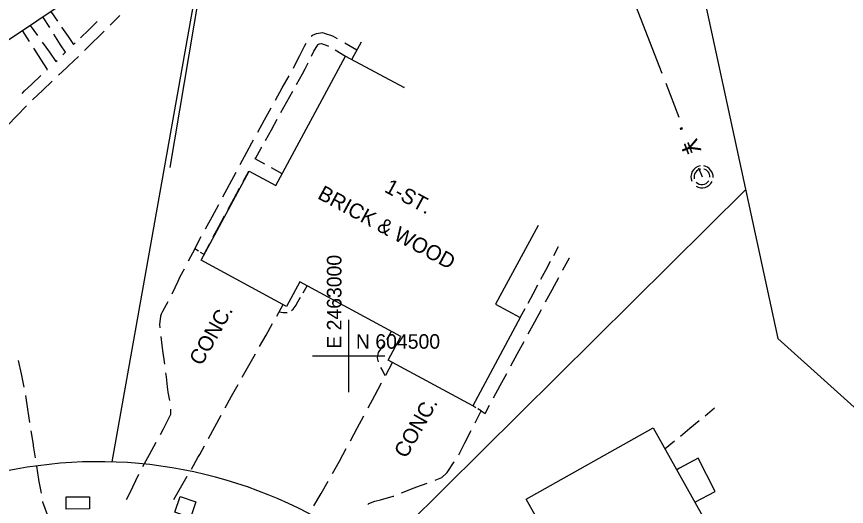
# Model space of a CAD drawing. Extents: x 2443269 to 2494951, y 591171 to 622130.
# Drawn here: x 2462908.5 to 2463137.2, y 604458.5 to 604593.6 of the extents above; entities that cross this region are included whole.
import ezdxf

# ---------------------------------------------------------------- set-up
doc = ezdxf.new("R2010")
doc.units = 0
for name, color, linetype in [('SURVEY - CENTERLINE - Existing Roads', 7, 'Continuous'), ('SURVEY - CONTROL - Grid', 7, 'Continuous'), ('SURVEY - CONTROL - Grid Text', 7, 'Continuous'), ('SURVEY - NON-TRANSPORTATION - Buildings', 7, 'Continuous'), ('SURVEY - NON-TRANSPORTATION - Buildings Text', 7, 'Continuous'), ('SURVEY - NON-TRANSPORTATION - Features', 7, 'Continuous'), ('SURVEY - PROPERTY - Property Lines', 7, 'Continuous'), ('SURVEY - PROPERTY - ROW Lines', 7, 'Continuous'), ('SURVEY - TRANSPORTATION - Features', 7, 'Continuous'), ('SURVEY - TRANSPORTATION - Features Text', 7, 'Continuous'), ('SURVEY - TRANSPORTATION - Roads', 7, 'Continuous'), ('SURVEY - UTILITIES - Cable (Underground) with Text', 7, 'Continuous'), ('SURVEY - UTILITIES - Poles and Miscellaneous with Text', 7, 'Continuous'), ('SURVEY - UTILITIES - Sanitary Sewer with Text', 7, 'Continuous')]:
    doc.layers.add(name, color=color, linetype=linetype)

# ---------------------------------------------------------------- blocks, each defined once
blk = doc.blocks.new('xlp')
at = {"layer": 'SURVEY - UTILITIES - Cable (Underground) with Text'}
for p, q in [((9.374, 2.317), (9.033, 2.131)), ((9.74, 2.449), (9.374, 2.317)), ((9.374, 2.317), (9.374, 2.317)), ((10.122, 2.523), (9.74, 2.449)), ((9.74, 2.449), (9.74, 2.449)), ((10.511, 2.538), (10.122, 2.523)), ((10.122, 2.523), (10.122, 2.523)), ((10.897, 2.493), (10.511, 2.538)), ((10.511, 2.538), (10.511, 2.538)), ((11.272, 2.39), (10.897, 2.493)), ((10.897, 2.493), (10.897, 2.493)), ((11.627, 2.231), (11.272, 2.39)), ((11.272, 2.39), (11.272, 2.39)), ((-2.285, -2.285), (-2.285, 2.285)), ((-2.285, 2.285), (-2.285, 2.285)), ((-2.285, 2.285), (2.285, 2.285)), ((2.285, 2.285), (2.285, -2.285)), ((2.285, 0), (7.873, 0)), ((7.94, 0.578), (7.881, 0.194)), ((7.881, 0.194), (7.881, 0.194)), ((7.881, 0.194), (7.881, -0.194)), ((8.058, 0.949), (7.94, 0.578)), ((7.94, 0.578), (7.94, 0.578)), ((8.23, 1.297), (8.058, 0.949)), ((8.058, 0.949), (8.058, 0.949)), ((8.454, 1.616), (8.23, 1.297)), ((8.23, 1.297), (8.23, 1.297)), ((8.724, 1.896), (8.454, 1.616)), ((8.454, 1.616), (8.454, 1.616)), ((9.033, 2.131), (8.724, 1.896)), ((8.724, 1.896), (8.724, 1.896)), ((9.033, 2.131), (9.033, 2.131)), ((11.953, 2.02), (11.627, 2.231)), ((11.627, 2.231), (11.627, 2.231)), ((12.244, 1.761), (11.953, 2.02)), ((11.953, 2.02), (11.953, 2.02)), ((12.491, 1.461), (12.244, 1.761)), ((12.244, 1.761), (12.244, 1.761)), ((12.69, 1.127), (12.491, 1.461)), ((12.491, 1.461), (12.491, 1.461)), ((12.835, 0.766), (12.69, 1.127)), ((12.69, 1.127), (12.69, 1.127)), ((12.924, 0.387), (12.835, 0.766)), ((12.835, 0.766), (12.835, 0.766)), ((12.953, 0), (12.924, 0.387)), ((12.924, 0.387), (12.924, 0.387)), ((12.924, -0.387), (12.953, 0)), ((2.285, -2.285), (-2.285, -2.285)), ((-2.285, -2.285), (-2.285, -2.285)), ((2.285, -2.285), (2.285, -2.285)), ((7.881, -0.194), (7.881, -0.194)), ((7.881, -0.194), (7.94, -0.578)), ((7.94, -0.578), (7.94, -0.578)), ((7.94, -0.578), (8.058, -0.949)), ((8.058, -0.949), (8.058, -0.949)), ((8.058, -0.949), (8.23, -1.297)), ((8.23, -1.297), (8.23, -1.297)), ((8.23, -1.297), (8.454, -1.616)), ((8.454, -1.616), (8.454, -1.616)), ((8.454, -1.616), (8.724, -1.896)), ((8.724, -1.896), (8.724, -1.896)), ((8.724, -1.896), (9.033, -2.131)), ((9.033, -2.131), (9.033, -2.131)), ((9.033, -2.131), (9.374, -2.317)), ((11.272, -2.39), (11.627, -2.231)), ((11.627, -2.231), (11.953, -2.02)), ((11.627, -2.231), (11.627, -2.231)), ((11.953, -2.02), (12.244, -1.761)), ((11.953, -2.02), (11.953, -2.02)), ((12.244, -1.761), (12.491, -1.461)), ((12.244, -1.761), (12.244, -1.761)), ((12.491, -1.461), (12.69, -1.127)), ((12.491, -1.461), (12.491, -1.461)), ((12.69, -1.127), (12.835, -0.766)), ((12.69, -1.127), (12.69, -1.127)), ((12.835, -0.766), (12.924, -0.387)), ((12.835, -0.766), (12.835, -0.766)), ((12.924, -0.387), (12.924, -0.387)), ((9.374, -2.317), (9.374, -2.317)), ((9.374, -2.317), (9.74, -2.449)), ((9.74, -2.449), (9.74, -2.449)), ((9.74, -2.449), (10.122, -2.523)), ((10.122, -2.523), (10.122, -2.523)), ((10.122, -2.523), (10.511, -2.538)), ((10.511, -2.538), (10.897, -2.493)), ((10.511, -2.538), (10.511, -2.538)), ((10.897, -2.493), (11.272, -2.39)), ((10.897, -2.493), (10.897, -2.493)), ((11.272, -2.39), (11.272, -2.39))]:
    blk.add_line(p, q, dxfattribs=at)
blk = doc.blocks.new('xmh')
at = {"layer": 'SURVEY - CENTERLINE - Existing Roads'}
for p, q in [((-1.773, 2.501), (-2.286, 2.034)), ((-1.171, 2.844), (-1.773, 2.501)), ((-1.773, 2.501), (-1.773, 2.501)), ((-0.508, 3.048), (-1.171, 2.844)), ((-1.171, 2.844), (-1.171, 2.844)), ((1.042, 2.883), (0.508, 3.048)), ((1.539, 2.628), (1.042, 2.883)), ((1.042, 2.883), (1.042, 2.883)), ((1.985, 2.291), (1.539, 2.628)), ((1.539, 2.628), (1.539, 2.628)), ((2.366, 1.882), (1.985, 2.291)), ((1.985, 2.291), (1.985, 2.291)), ((-2.948, 0.825), (-3.065, 0.141)), ((-3.065, 0.141), (-3.065, 0.141)), ((-3.065, 0.141), (-3.03, -0.551)), ((-2.684, 1.466), (-2.948, 0.825)), ((-2.948, 0.825), (-2.948, 0.825)), ((-2.286, 2.034), (-2.684, 1.466)), ((-2.684, 1.466), (-2.684, 1.466)), ((-2.286, 2.034), (-2.286, 2.034)), ((-2.167, 0.395), (-2.198, -0.058)), ((-2.039, 0.831), (-2.167, 0.395)), ((-2.167, 0.395), (-2.167, 0.395)), ((-1.822, 1.23), (-2.039, 0.831)), ((-2.039, 0.831), (-2.039, 0.831)), ((-1.525, 1.574), (-1.822, 1.23)), ((-1.822, 1.23), (-1.822, 1.23)), ((-1.161, 1.847), (-1.525, 1.574)), ((-1.525, 1.574), (-1.525, 1.574)), ((-0.748, 2.036), (-1.161, 1.847)), ((-1.161, 1.847), (-1.161, 1.847)), ((-0.304, 2.133), (-0.748, 2.036)), ((-0.748, 2.036), (-0.748, 2.036)), ((0.864, 2.014), (0.508, 2.133)), ((1.194, 1.835), (0.864, 2.014)), ((0.864, 2.014), (0.864, 2.014)), ((1.487, 1.599), (1.194, 1.835)), ((1.194, 1.835), (1.194, 1.835)), ((1.734, 1.316), (1.487, 1.599)), ((1.487, 1.599), (1.487, 1.599)), ((1.927, 0.994), (1.734, 1.316)), ((1.734, 1.316), (1.734, 1.316)), ((2.061, 0.643), (1.927, 0.994)), ((1.927, 0.994), (1.927, 0.994)), ((2.13, 0.274), (2.061, 0.643)), ((2.061, 0.643), (2.061, 0.643)), ((2.133, -0.101), (2.13, 0.274)), ((2.13, 0.274), (2.13, 0.274)), ((2.671, 1.413), (2.366, 1.882)), ((2.366, 1.882), (2.366, 1.882)), ((2.89, 0.899), (2.671, 1.413)), ((2.671, 1.413), (2.671, 1.413)), ((3.017, 0.354), (2.89, 0.899)), ((2.89, 0.899), (2.89, 0.899)), ((3.048, -0.203), (3.017, 0.354)), ((3.017, 0.354), (3.017, 0.354)), ((-3.03, -0.551), (-3.03, -0.551)), ((-3.03, -0.551), (-2.844, -1.219)), ((-2.198, -0.058), (-2.198, -0.058)), ((-2.198, -0.058), (-2.133, -0.508)), ((-1.625, -1.422), (-1.25, -1.756)), ((-1.25, -1.756), (-1.25, -1.756)), ((-1.25, -1.756), (-0.808, -1.995)), ((-0.808, -1.995), (-0.808, -1.995)), ((-0.808, -1.995), (-0.323, -2.125)), ((-0.323, -2.125), (-0.323, -2.125)), ((-0.323, -2.125), (0.178, -2.14)), ((0.178, -2.14), (0.67, -2.038)), ((0.178, -2.14), (0.178, -2.14)), ((0.67, -2.038), (1.125, -1.825)), ((0.67, -2.038), (0.67, -2.038)), ((1.125, -1.825), (1.518, -1.512)), ((1.125, -1.825), (1.125, -1.825)), ((1.518, -1.512), (1.828, -1.117)), ((1.518, -1.512), (1.518, -1.512)), ((1.958, -2.32), (2.403, -1.862)), ((2.403, -1.862), (2.743, -1.32)), ((2.403, -1.862), (2.403, -1.862)), ((-1.625, -2.54), (-1.054, -2.827)), ((-1.054, -2.827), (-1.054, -2.827)), ((-1.054, -2.827), (-0.436, -2.988)), ((-0.436, -2.988), (-0.436, -2.988)), ((-0.436, -2.988), (0.202, -3.016)), ((0.202, -3.016), (0.832, -2.91)), ((0.202, -3.016), (0.202, -3.016)), ((0.832, -2.91), (1.426, -2.675)), ((0.832, -2.91), (0.832, -2.91)), ((1.426, -2.675), (1.958, -2.32)), ((1.426, -2.675), (1.426, -2.675)), ((1.958, -2.32), (1.958, -2.32))]:
    blk.add_line(p, q, dxfattribs=at)

msp = doc.modelspace()

# ---------------------------------------------------------------- linework, layer by layer
at = {"layer": 'SURVEY - CONTROL - Grid'}
for p, q in [((2463000, 604490), (2463000, 604510)), ((2462990, 604500), (2463010, 604500))]:
    msp.add_line(p, q, dxfattribs=at)
at = {"layer": 'SURVEY - NON-TRANSPORTATION - Buildings'}
for points in [[(2462848.145, 604606.514), (2462872.072, 604622.541), (2462871.238, 604623.785), (2462901.603, 604644.126), (2462902.741, 604642.423), (2462925.864, 604657.912), (2462953.292, 604616.967), (2462929.568, 604601.075), (2462928.768, 604602.269), (2462899.28, 604582.515), (2462899.709, 604581.872), (2462875.51, 604565.661)], [(2463082.619, 604400.324), (2463048.889, 604460.498), (2463083.948, 604480.15), (2463117.678, 604419.976)]]:
    msp.add_lwpolyline(points, close=True, dxfattribs=at)
msp.add_lwpolyline([(2463052.212, 604535.993), (2463040.48, 604514.247), (2463047.311, 604510.563), (2463034.188, 604486.239), (2463010.864, 604498.821), (2463014.414, 604505.402), (2462986.553, 604520.435), (2462982.905, 604513.67), (2462959.335, 604526.387)], dxfattribs=at)
at = {"layer": 'SURVEY - NON-TRANSPORTATION - Buildings Text'}
msp.add_lwpolyline([(2462959.335, 604526.387), (2462972.613, 604550.996), (2462979.913, 604547.059), (2462999.158, 604582.732), (2463015.251, 604574.051), (2463015.339, 604574.215)], dxfattribs=at)
at = {"layer": 'SURVEY - NON-TRANSPORTATION - Features'}
for p, q in [((2462950.766, 604551.977), (2462963.315, 604626.111)), ((2463003.426, 604586.567), (2463000.851, 604581.908)), ((2463091.153, 604469.08), (2463090.441, 604468.568))]:
    msp.add_line(p, q, dxfattribs=at)
msp.add_lwpolyline([(2463095.408, 604459.704), (2463101.064, 604462.633), (2463096.336, 604471.764), (2463091.153, 604469.08)], dxfattribs=at)
msp.add_lwpolyline([(2462922.121, 604461.101), (2462928.535, 604461.154), (2462928.561, 604457.837), (2462922.147, 604457.784)], close=True, dxfattribs=at)
at = {"layer": 'SURVEY - PROPERTY - Property Lines'}
for p, q in [((2462934.798, 604470.777), (2462984.933, 604752.663)), ((2463007.39, 604444.738), (2463109.405, 604545.802))]:
    msp.add_line(p, q, dxfattribs=at)
msp.add_lwpolyline([(2462970.603, 604768.156), (2463088.693, 604641.661), (2463118.316, 604504.82), (2463394.014, 604256.663)], dxfattribs=at)
at = {"layer": 'SURVEY - PROPERTY - ROW Lines'}
msp.add_arc((2462930.948, 604345.836), 124.999, 41.29809, 131.29837, dxfattribs=at)
at = {"layer": 'SURVEY - TRANSPORTATION - Features'}
for p, q in [((2462917.905, 604594.992), (2462919.734, 604592.358)), ((2462917.583, 604590.591), (2462915.723, 604593.529)), ((2462915.723, 604593.529), (2462915.723, 604593.529)), ((2462934.23, 604591.216), (2462936.897, 604593.881)), ((2462912.229, 604591.19), (2462914.247, 604588.357)), ((2462920.877, 604590.711), (2462922.706, 604588.077)), ((2462928.37, 604589.998), (2462930.639, 604592.265)), ((2462911.986, 604586.727), (2462910.044, 604589.726)), ((2462910.044, 604589.726), (2462910.044, 604589.726)), ((2462920.606, 604585.816), (2462918.746, 604588.754)), ((2462922.706, 604588.077), (2462924.185, 604585.947)), ((2462926.066, 604587.768), (2462928.364, 604589.992)), ((2462928.364, 604589.992), (2462928.37, 604589.998)), ((2462930.664, 604587.653), (2462932.563, 604589.55)), ((2462989.693, 604588.185), (2462990.031, 604588.516)), ((2462990.031, 604588.516), (2462991.13, 604588.959)), ((2462991.13, 604588.959), (2462992.777, 604589.215)), ((2462992.777, 604589.215), (2462993.277, 604589.042)), ((2462993.277, 604589.042), (2462995.503, 604588.273)), ((2462995.503, 604588.273), (2462996.807, 604587.535)), ((2462915.508, 604586.587), (2462917.526, 604583.755)), ((2462921.914, 604583.749), (2462920.606, 604585.816)), ((2462924.185, 604585.947), (2462924.626, 604586.374)), ((2462927.174, 604584.275), (2462929.884, 604586.898)), ((2462929.884, 604586.898), (2462930.664, 604587.653)), ((2462987.81, 604585.438), (2462988.293, 604586.248)), ((2462990.405, 604584.024), (2462991.38, 604585.656)), ((2462991.38, 604585.656), (2462991.448, 604585.77)), ((2462991.448, 604585.77), (2462991.678, 604585.996)), ((2462991.678, 604585.996), (2462991.917, 604586.094)), ((2462991.917, 604586.094), (2462992.505, 604586.183)), ((2462992.505, 604586.183), (2462994.293, 604585.566)), ((2462994.293, 604585.566), (2462994.435, 604585.483)), ((2462998.902, 604586.349), (2463002.255, 604584.451)), ((2462915.141, 604581.854), (2462913.199, 604584.853)), ((2462917.526, 604583.755), (2462919.309, 604581.252)), ((2462921.173, 604583.032), (2462921.914, 604583.749)), ((2462986.517, 604582.831), (2462987.81, 604585.438)), ((2462989.755, 604582.713), (2462990.405, 604584.024)), ((2462996.251, 604584.425), (2462999.158, 604582.732)), ((2463002.255, 604584.451), (2463002.255, 604584.451)), ((2462916.96, 604579.044), (2462915.141, 604581.854)), ((2462919.309, 604581.252), (2462919.604, 604581.529)), ((2462922.771, 604580.015), (2462925.481, 604582.637)), ((2462985.382, 604580.54), (2462986.517, 604582.831)), ((2462999.158, 604582.732), (2462999.158, 604582.732)), ((2462916.796, 604578.89), (2462916.96, 604579.044)), ((2462920.03, 604577.426), (2462922.328, 604579.585)), ((2462922.328, 604579.585), (2462922.771, 604580.015)), ((2462984.752, 604579.407), (2462985.382, 604580.54)), ((2462987.265, 604577.849), (2462987.997, 604579.165)), ((2462987.997, 604579.165), (2462988.822, 604580.83)), ((2462912.566, 604574.913), (2462915.169, 604577.36)), ((2462981.71, 604573.935), (2462983.582, 604577.303)), ((2462985.631, 604574.908), (2462987.265, 604577.849)), ((2462910.658, 604573.119), (2462912.566, 604574.913)), ((2462915.566, 604573.229), (2462918.313, 604575.811)), ((2462909.994, 604572.435), (2462910.658, 604573.119)), ((2462912.961, 604570.78), (2462915.566, 604573.229)), ((2462979.839, 604570.567), (2462981.71, 604573.935)), ((2462982.975, 604570.13), (2462984.609, 604573.071)), ((2462912.825, 604570.64), (2462912.961, 604570.78)), ((2462981.341, 604567.19), (2462982.975, 604570.13)), ((2462908.559, 604566.242), (2462911.184, 604568.948)), ((2462976.797, 604565.095), (2462978.669, 604568.462)), ((2462905.934, 604563.536), (2462908.559, 604566.242)), ((2462974.925, 604561.727), (2462976.797, 604565.095)), ((2462978.685, 604562.412), (2462980.319, 604565.352)), ((2462977.051, 604559.472), (2462978.685, 604562.412)), ((2462971.918, 604556.235), (2462973.282, 604558.772)), ((2462973.282, 604558.772), (2462973.755, 604559.622)), ((2462970.094, 604552.841), (2462971.918, 604556.235)), ((2462974.432, 604554.674), (2462975.874, 604557.354)), ((2462975.874, 604557.354), (2462976.029, 604557.634)), ((2462974.247, 604554.329), (2462974.432, 604554.674)), ((2462976.848, 604552.89), (2462974.247, 604554.329)), ((2462981.632, 604550.245), (2462978.688, 604551.873)), ((2462967.129, 604547.327), (2462968.954, 604550.72)), ((2462970.887, 604548.078), (2462972.449, 604550.983)), ((2462972.449, 604550.983), (2462972.449, 604550.983)), ((2462965.305, 604543.933), (2462967.129, 604547.327)), ((2462968.349, 604543.358), (2462969.911, 604546.263)), ((2462966.787, 604540.454), (2462968.349, 604543.358)), ((2462962.34, 604538.418), (2462964.164, 604541.812)), ((2462960.515, 604535.025), (2462962.34, 604538.418)), ((2462964.249, 604535.734), (2462965.811, 604538.638)), ((2462962.687, 604532.829), (2462964.249, 604535.734)), ((2462957.551, 604529.51), (2462959.375, 604532.904)), ((2462960.149, 604528.109), (2462961.711, 604531.014)), ((2462957.551, 604529.51), (2462955.741, 604526.108)), ((2462958.563, 604528.936), (2462957.551, 604529.51)), ((2462957.551, 604529.51), (2462957.551, 604529.51)), ((2462960.208, 604528.004), (2462959.196, 604528.578)), ((2463056.511, 604527.663), (2463057.849, 604530.15)), ((2463057.849, 604530.15), (2463057.849, 604530.15)), ((2463054.336, 604523.621), (2463055.674, 604526.108)), ((2463059.046, 604523.713), (2463060.828, 604527.062)), ((2463060.828, 604527.062), (2463060.828, 604527.062)), ((2462954.61, 604523.982), (2462953.45, 604521.8)), ((2462953.45, 604521.8), (2462952.869, 604520.547)), ((2463052.998, 604521.134), (2463054.336, 604523.621)), ((2463056.085, 604518.245), (2463057.902, 604521.599)), ((2463059.037, 604523.695), (2463059.046, 604523.713)), ((2462952.869, 604520.547), (2462951.248, 604517.051)), ((2462987.443, 604517.417), (2462988.558, 604519.352)), ((2462988.558, 604519.352), (2462988.558, 604519.352)), ((2463050.824, 604517.092), (2463052.162, 604519.579)), ((2463049.485, 604514.605), (2463050.824, 604517.092)), ((2463054.269, 604514.891), (2463056.085, 604518.245)), ((2462950.194, 604514.888), (2462948.696, 604512.272)), ((2462985.632, 604514.272), (2462986.747, 604516.207)), ((2462980.156, 604510.974), (2462981.963, 604514.179)), ((2462981.963, 604514.179), (2462981.963, 604514.179)), ((2462984.26, 604512.538), (2462984.739, 604512.922)), ((2462984.739, 604512.922), (2462985.48, 604514.008)), ((2462985.48, 604514.008), (2462985.632, 604514.272)), ((2463047.311, 604510.563), (2463048.649, 604513.05)), ((2463051.317, 604509.442), (2463053.134, 604512.795)), ((2462948.131, 604510.999), (2462947.833, 604508.631)), ((2462948.356, 604511.505), (2462948.131, 604510.999)), ((2462948.696, 604512.272), (2462948.356, 604511.505)), ((2462980.808, 604512.131), (2462981.901, 604511.948)), ((2462981.901, 604511.948), (2462982.629, 604511.941)), ((2462982.629, 604511.941), (2462983.022, 604512.002)), ((2462947.833, 604508.631), (2462947.94, 604507.725)), ((2462977.22, 604505.768), (2462979.027, 604508.972)), ((2463049.501, 604506.088), (2463051.317, 604509.442)), ((2462975.414, 604502.564), (2462977.22, 604505.768)), ((2463010.518, 604504.519), (2463011.793, 604506.816)), ((2462948.222, 604505.333), (2462948.502, 604502.968)), ((2463046.549, 604500.638), (2463048.366, 604503.992)), ((2462948.502, 604502.968), (2462948.698, 604501.51)), ((2462948.698, 604501.51), (2462949.213, 604497.692)), ((2463007.957, 604499.441), (2463008.233, 604500.922)), ((2463008.233, 604500.922), (2463008.246, 604500.99)), ((2463008.246, 604500.99), (2463009.69, 604503.103)), ((2462908.931, 604498.739), (2462909.694, 604495.056)), ((2462972.478, 604497.357), (2462974.284, 604500.561)), ((2463008.216, 604498.351), (2463007.957, 604499.441)), ((2463044.733, 604497.284), (2463046.549, 604500.638)), ((2462970.671, 604494.153), (2462972.478, 604497.357)), ((2463009.286, 604496.052), (2463008.876, 604496.856)), ((2463010.207, 604494.724), (2463012.062, 604498.175)), ((2463012.062, 604498.175), (2463012.062, 604498.175)), ((2462909.694, 604495.056), (2462910.458, 604491.373)), ((2462949.534, 604495.305), (2462949.683, 604494.198)), ((2462949.683, 604494.198), (2462950.006, 604491.481)), ((2463010.103, 604494.533), (2463009.286, 604496.052)), ((2463041.781, 604491.834), (2463043.597, 604495.188)), ((2462968.066, 604489.533), (2462969.541, 604492.15)), ((2463007.194, 604489.117), (2463009.048, 604492.567)), ((2463039.965, 604488.481), (2463041.781, 604491.834)), ((2462950.006, 604491.481), (2462950.182, 604489.996)), ((2462950.182, 604489.996), (2462950.59, 604487.674)), ((2462967.742, 604488.942), (2462968.066, 604489.533)), ((2462910.893, 604489.064), (2462911.475, 604485.348)), ((2462965.978, 604485.714), (2462967.742, 604488.942)), ((2463005.339, 604485.666), (2463007.194, 604489.117)), ((2462911.475, 604485.348), (2462912.057, 604481.633)), ((2462950.86, 604485.283), (2462950.845, 604483.877)), ((2463035.085, 604485.713), (2463034.188, 604486.239)), ((2463034.188, 604486.239), (2463034.188, 604486.239)), ((2463034.836, 604481.511), (2463036.543, 604484.858)), ((2463036.543, 604484.858), (2463035.646, 604485.384)), ((2463036.543, 604484.858), (2463036.543, 604484.858)), ((2463036.543, 604484.858), (2463037.626, 604484.162)), ((2463037.626, 604484.162), (2463038.829, 604486.384)), ((2463100.867, 604485.557), (2463098.263, 604483.423)), ((2462950.845, 604483.877), (2462949.787, 604481.671)), ((2462963.111, 604480.469), (2462964.876, 604483.697)), ((2463002.326, 604480.059), (2463004.18, 604483.509)), ((2462949.787, 604481.671), (2462948.886, 604479.792)), ((2462961.347, 604477.241), (2462963.111, 604480.469)), ((2463096.636, 604482.089), (2463094.032, 604479.955)), ((2462912.42, 604479.31), (2462913.002, 604475.595)), ((2462948.886, 604479.792), (2462948.029, 604478.244)), ((2463000.472, 604476.608), (2463002.326, 604480.059)), ((2463032.062, 604476.072), (2463033.769, 604479.419)), ((2463094.032, 604479.955), (2463091.428, 604477.82)), ((2462946.863, 604476.137), (2462944.997, 604472.766)), ((2463030.355, 604472.725), (2463032.062, 604476.072)), ((2463089.8, 604476.487), (2463087.196, 604474.353)), ((2462913.062, 604475.206), (2462913.579, 604471.878)), ((2462958.942, 604472.84), (2462960.245, 604475.224)), ((2462997.458, 604471), (2462999.313, 604474.451)), ((2463087.196, 604474.353), (2463087.196, 604474.353)), ((2462944.997, 604472.766), (2462943.132, 604469.394)), ((2462956.637, 604468.812), (2462958.464, 604472.005)), ((2462958.464, 604472.005), (2462958.942, 604472.84)), ((2462913.94, 604469.555), (2462914.509, 604465.885)), ((2462995.562, 604467.573), (2462996.317, 604468.877)), ((2462996.317, 604468.877), (2462997.458, 604471)), ((2463027.144, 604467.896), (2463029.077, 604470.758)), ((2462942.022, 604467.258), (2462940.371, 604463.777)), ((2462953.668, 604463.624), (2462955.495, 604466.817)), ((2463025.667, 604466.452), (2463026.927, 604467.684)), ((2463026.927, 604467.684), (2463027.144, 604467.896)), ((2462914.509, 604465.885), (2462914.518, 604465.839)), ((2462914.518, 604465.839), (2462915.193, 604462.139)), ((2462992.371, 604462.065), (2462994.334, 604465.455)), ((2463018.797, 604463.883), (2463021.599, 604464.931)), ((2463023.798, 604465.753), (2463025.667, 604466.452)), ((2462940.371, 604463.777), (2462939.102, 604461.105)), ((2462951.841, 604460.432), (2462953.668, 604463.624)), ((2462990.407, 604458.675), (2462992.371, 604462.065)), ((2463014.592, 604462.219), (2463018.085, 604463.601)), ((2463018.085, 604463.601), (2463018.797, 604463.883)), ((2462915.628, 604459.759), (2462916.868, 604456.282)), ((2462939.102, 604461.105), (2462938.669, 604460.322)), ((2463005.516, 604459.284), (2463007.167, 604459.904)), ((2463007.167, 604459.904), (2463008.789, 604460.348)), ((2463008.789, 604460.348), (2463012.291, 604461.308)), ((2463012.291, 604461.308), (2463012.408, 604461.354)), ((2463005.311, 604459.049), (2463005.516, 604459.284))]:
    msp.add_line(p, q, dxfattribs=at)
at = {"layer": 'SURVEY - TRANSPORTATION - Roads'}
for p, q in [((2462913.002, 604475.595), (2462913.062, 604475.206)), ((2462915.616, 604459.827), (2462915.628, 604459.759))]:
    msp.add_line(p, q, dxfattribs=at)
at = {"layer": 'SURVEY - UTILITIES - Sanitary Sewer with Text'}
for p, q in [((2463079.094, 604596.655), (2463086.322, 604578.007)), ((2463087.407, 604575.21), (2463091.021, 604565.886)), ((2463096.442, 604551.9), (2463097.41, 604549.403))]:
    msp.add_line(p, q, dxfattribs=at)

# ---------------------------------------------------------------- block references
at = {"layer": 'SURVEY - UTILITIES - Poles and Miscellaneous with Text', "rotation": -108.82169980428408}
msp.add_blockref('xlp', (2462954.936, 604458.293), dxfattribs=at)
at = {"layer": 'SURVEY - UTILITIES - Sanitary Sewer with Text'}
msp.add_blockref('xmh', (2463097.41, 604549.403), dxfattribs=at)

# ---------------------------------------------------------------- texts
at = {"layer": 'SURVEY - CONTROL - Grid Text'}
msp.add_text('E 2463000', height=4, rotation=90, dxfattribs=at).set_placement((2462998, 604502))
msp.add_text('N 604500', height=4, dxfattribs=at).set_placement((2463002, 604502))
at = {"layer": 'SURVEY - NON-TRANSPORTATION - Buildings Text'}
for s, p in [('BRICK & WOOD', (2462991.147, 604543.564)), ('1-ST.', (2463009.577, 604545.407))]:
    msp.add_text(s, height=4.166, rotation=331.65018, dxfattribs=at).set_placement(p)
at = {"layer": 'SURVEY - TRANSPORTATION - Features Text'}
for p in [(2462959.426, 604497.064), (2463015.887, 604471.534)]:
    msp.add_text('CONC.', height=4.166, rotation=60.58139, dxfattribs=at).set_placement(p)
at = {"layer": 'SURVEY - UTILITIES - Sanitary Sewer with Text'}
for s, p in [('·', (2463089.443, 604563.04)), ('¥', (2463091.25, 604558.378))]:
    msp.add_text(s, height=5, rotation=291.18776, dxfattribs=at).set_placement(p)

doc.saveas('drawing.dxf')
